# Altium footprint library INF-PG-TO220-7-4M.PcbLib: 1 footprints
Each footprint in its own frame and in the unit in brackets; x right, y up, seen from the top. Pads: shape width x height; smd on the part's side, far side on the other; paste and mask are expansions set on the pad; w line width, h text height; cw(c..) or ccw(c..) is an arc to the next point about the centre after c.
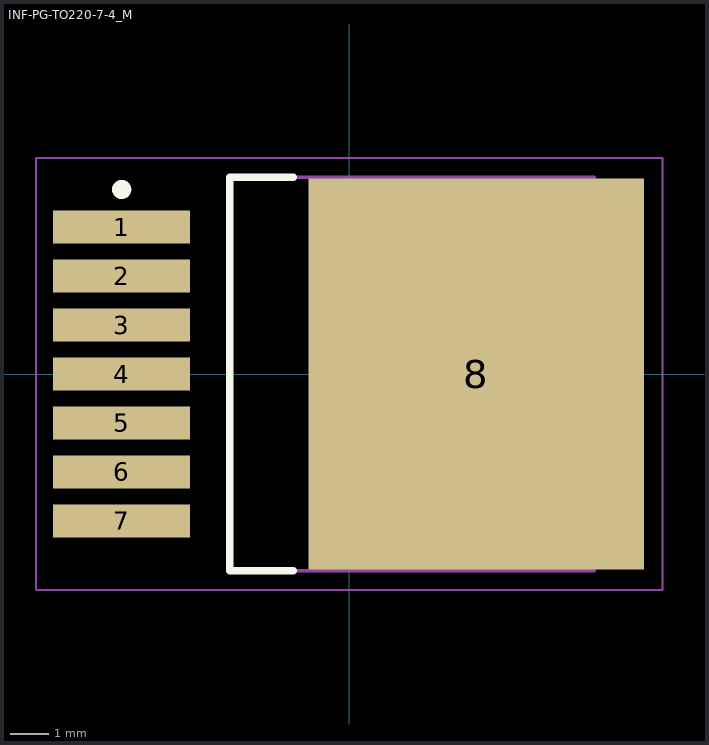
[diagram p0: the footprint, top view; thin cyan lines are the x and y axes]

## INF-PG-TO220-7-4_M [mm] "DPAK, 7-Leads, Body 10x9.25mm, Pitch 1.27mm, IPC Low Density"
height 4.4
pads (8):
  rect 3.55x0.85 smd: 1(-5.9,3.81) 2(-5.9,2.54) 3(-5.9,1.27) 4(-5.9,0) 5(-5.9,-1.27) 6(-5.9,-2.54) 7(-5.9,-3.81)
  rect 8.7x10.15 smd: 8(3.3,0)
Top Overlay:
  circle w0.25: c-5.9,4.785 r0.125
  lines w0.2: -1.45,-5.1 -3.1,-5.1 -3.1,5.1 -1.45,5.1
Mechanical 13:
  lines w0.1: -3.1,-5.1 6.35,-5.1 6.35,5.1 -3.1,5.1 -3.1,-5.1
Mechanical 15:
  lines w0.05: -8.125,-5.6 8.125,-5.6 8.125,5.6 -8.125,5.6 -8.125,-5.6
  lines w0.1: -0.5,0 0.5,0 ; 0,-0.5 0,0.5
3D body: height 4.4, standoff 0.1, extent -3.1,-5.1 6.35,5.1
